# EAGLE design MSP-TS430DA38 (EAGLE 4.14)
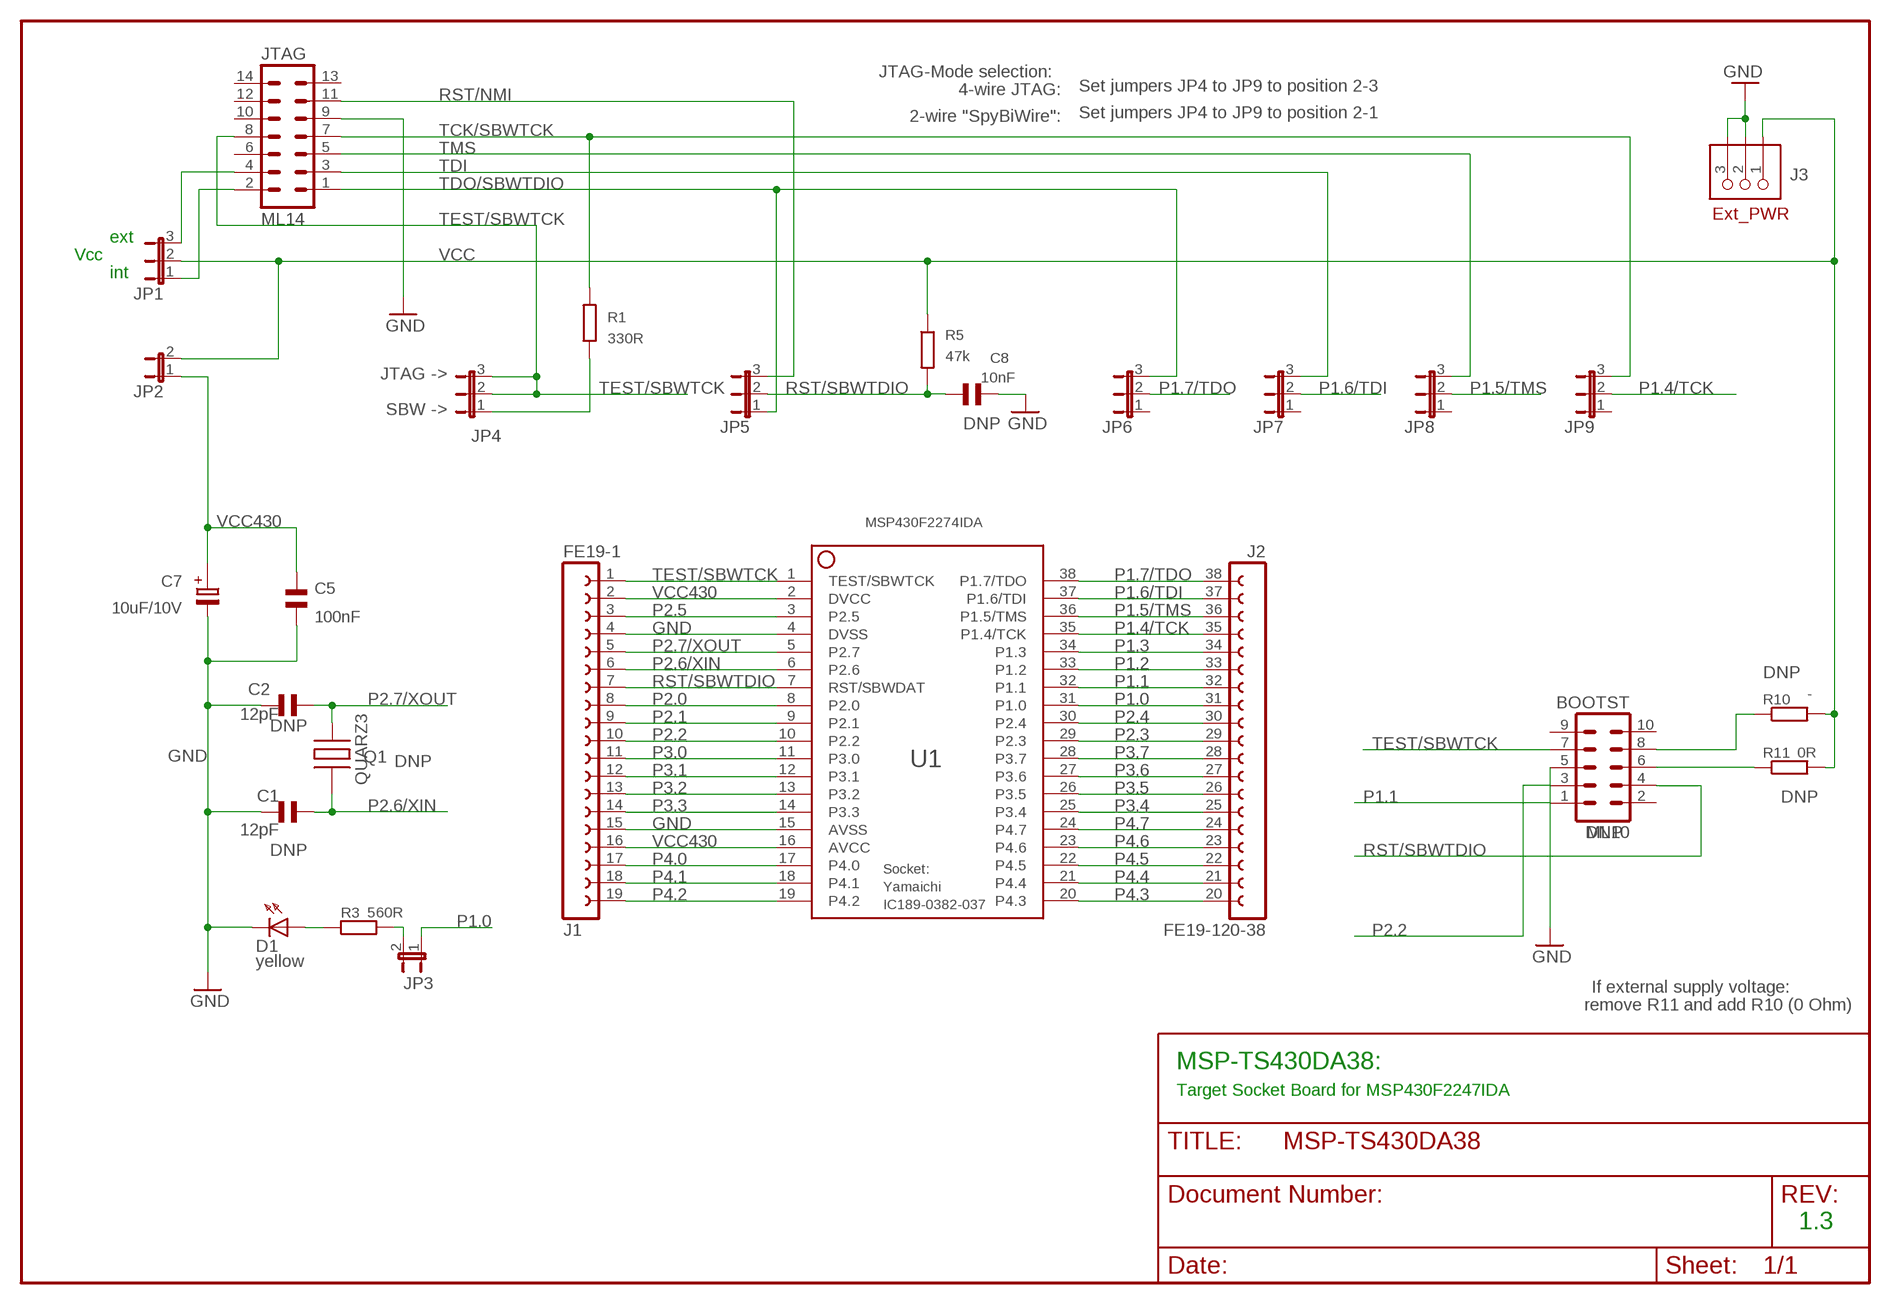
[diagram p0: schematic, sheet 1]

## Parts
BOOTST  ML10  [ML10]
C1  12pF  CSMD0805  [CSMD0805]
C2  12pF  CSMD0805  [CSMD0805]
C5  100nF  CSMD0805  [CSMD0805]
C7  10uF/10V  ELKO_1210  [1210ELKO]
C8  10nF  CSMD0805  [CSMD0805]
D1  yellow  LED_0805  [DIODE0805]
J1  FE19-1  [FE19-1-1]
J2  FE19-120-38  [FE19-2]
J3  PINHD-1X3  [PWR3]
JP1  JP2E  [JP2]
JP2  JP1E  [JP1]
JP3  JP1E  [JP1]
JP4  JP2E  [JP2]
JP5  JP2E  [JP2]
JP6  JP2E  [JP2]
JP7  JP2E  [JP2]
JP8  JP2E  [JP2]
JP9  JP2E  [JP2]
JTAG  ML14  [ML14]
Q1  QUARZ3  [QUARZ3]
R1  330R  R_0805  [0805]
R3  560R  R_0805  [0805]
R5  47k  R_0805  [0805]
R10  -  R_0805  [0805]
R11  0R  R_0805  [0805]
U1  MSP430F2274IDA  F2274_DA38  [IC189-0382-037]

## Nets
GND: BOOTST.5 C1.2 C2.2 C5.2 C7.- C8.1 D1.K(C) J1.4 J1.15 J3.2 J3.3 JTAG.9 U1.4(DVSS) U1.15(AVSS)
N$1: D1.A R3.1
N$2: JP4.1 R1.1
N$7: JP1.1 JTAG.2
N$23: JP1.3 JTAG.4
N$33: JP3.2 R3.2
N$42: BOOTST.8 R10.1
N$49: BOOTST.6 R11.1
P1.0: J2.31 JP3.1 U1.31(P1.0)
P1.1: BOOTST.1 J2.32 U1.32(P1.1)
P1.2: J2.33 U1.33(P1.2)
P1.3: J2.34 U1.34(P1.3)
P1.4/TCK: J2.35 JP9.2 U1.35(P1.4/TCK)
P1.5/TMS: J2.36 JP8.2 U1.36(P1.5/TMS)
P1.6/TDI: J2.37 JP7.2 U1.37(P1.6/TDI)
P1.7/TDO: J2.38 JP6.2 U1.38(P1.7/TDO)
P2.0: J1.8 U1.8(P2.0)
P2.1: J1.9 U1.9(P2.1)
P2.2: BOOTST.3 J1.10 U1.10(P2.2)
P2.3: J2.29 U1.29(P2.3)
P2.4: J2.30 U1.30(P2.4)
P2.5: J1.3 U1.3(P2.5)
P2.6/XIN: C1.1 J1.6 Q1.3 U1.6(P2.6)
P2.7/XOUT: C2.1 J1.5 Q1.4 U1.5(P2.7)
P3.0: J1.11 U1.11(P3.0)
P3.1: J1.12 U1.12(P3.1)
P3.2: J1.13 U1.13(P3.2)
P3.3: J1.14 U1.14(P3.3)
P3.4: J2.25 U1.25(P3.4)
P3.5: J2.26 U1.26(P3.5)
P3.6: J2.27 U1.27(P3.6)
P3.7: J2.28 U1.28(P3.7)
P4.0: J1.17 U1.17(P4.0)
P4.1: J1.18 U1.18(P4.1)
P4.2: J1.19 U1.19(P4.2)
P4.3: J2.20 U1.20(P4.3)
P4.4: J2.21 U1.21(P4.4)
P4.5: J2.22 U1.22(P4.5)
P4.6: J2.23 U1.23(P4.6)
P4.7: J2.24 U1.24(P4.7)
RST/NMI: JP5.3 JTAG.11
RST/SBWTDIO: BOOTST.4 C8.2 J1.7 JP5.2 R5.2 U1.7(RST/SBWDAT)
TCK/SBWTCK: JP9.3 JTAG.7 R1.2
TDI: JP7.3 JTAG.3
TDO/SBWTDIO: JP5.1 JP6.3 JTAG.1
TEST/SBWTCK: BOOTST.7 J1.1 JP4.2 JP4.3 JTAG.8 U1.1(TEST/SBWTCK)
TMS: JP8.3 JTAG.5
VCC: J3.1 JP1.2 JP2.2 R5.1 R10.2 R11.2
VCC430: C5.1 C7.+ J1.2 J1.16 JP2.1 U1.2(DVCC) U1.16(AVCC)
Unconnected: BOOTST.2 BOOTST.9 BOOTST.10 JP6.1 JP7.1 JP8.1 JP9.1 JTAG.6 JTAG.10 JTAG.12 JTAG.13 JTAG.14

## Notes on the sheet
- JTAG-Mode selection:
- 4-wire JTAG:
- Set jumpers JP4 to JP9 to position 2-3
- 2-wire "SpyBiWire":
- Set jumpers JP4 to JP9 to position 2-1
- Ext_PWR
- ext
- Vcc
- int
- JTAG ->
- SBW ->
- DNP
- DNP
- DNP
- DNP
- DNP
- DNP
- DNP
- Socket:
- Yamaichi
- IC189-0382-037
- If external supply voltage:
- remove R11 and add R10 (0 Ohm)
- MSP-TS430DA38:
- Target Socket Board for MSP430F2247IDA
- 1.3

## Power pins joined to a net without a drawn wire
GND: Q1.GND@1(GND) Q1.GND@2(GND) Q1.GND@3(GND)

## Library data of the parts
BOOTST = con-ml:ML10
C1 C2 C5 C8 = cap:CSMD0805
C7 = smd:ELKO_1210
D1 = smd:LED_0805
J1 J2 = con-lsta_extended:FE19-1
J3 = PINHEAD:PINHD-1X3
JP1 JP4-JP9 = jumper:JP2E: JUMPER
JP2 JP3 = jumper:JP1E: JUMPER
JTAG = con-ml:ML14
Q1 = MSP430:QUARZ3
R1 R3 R5 R10 R11 = smd:R_0805
U1 = yamaichi_new:F2274_DA38

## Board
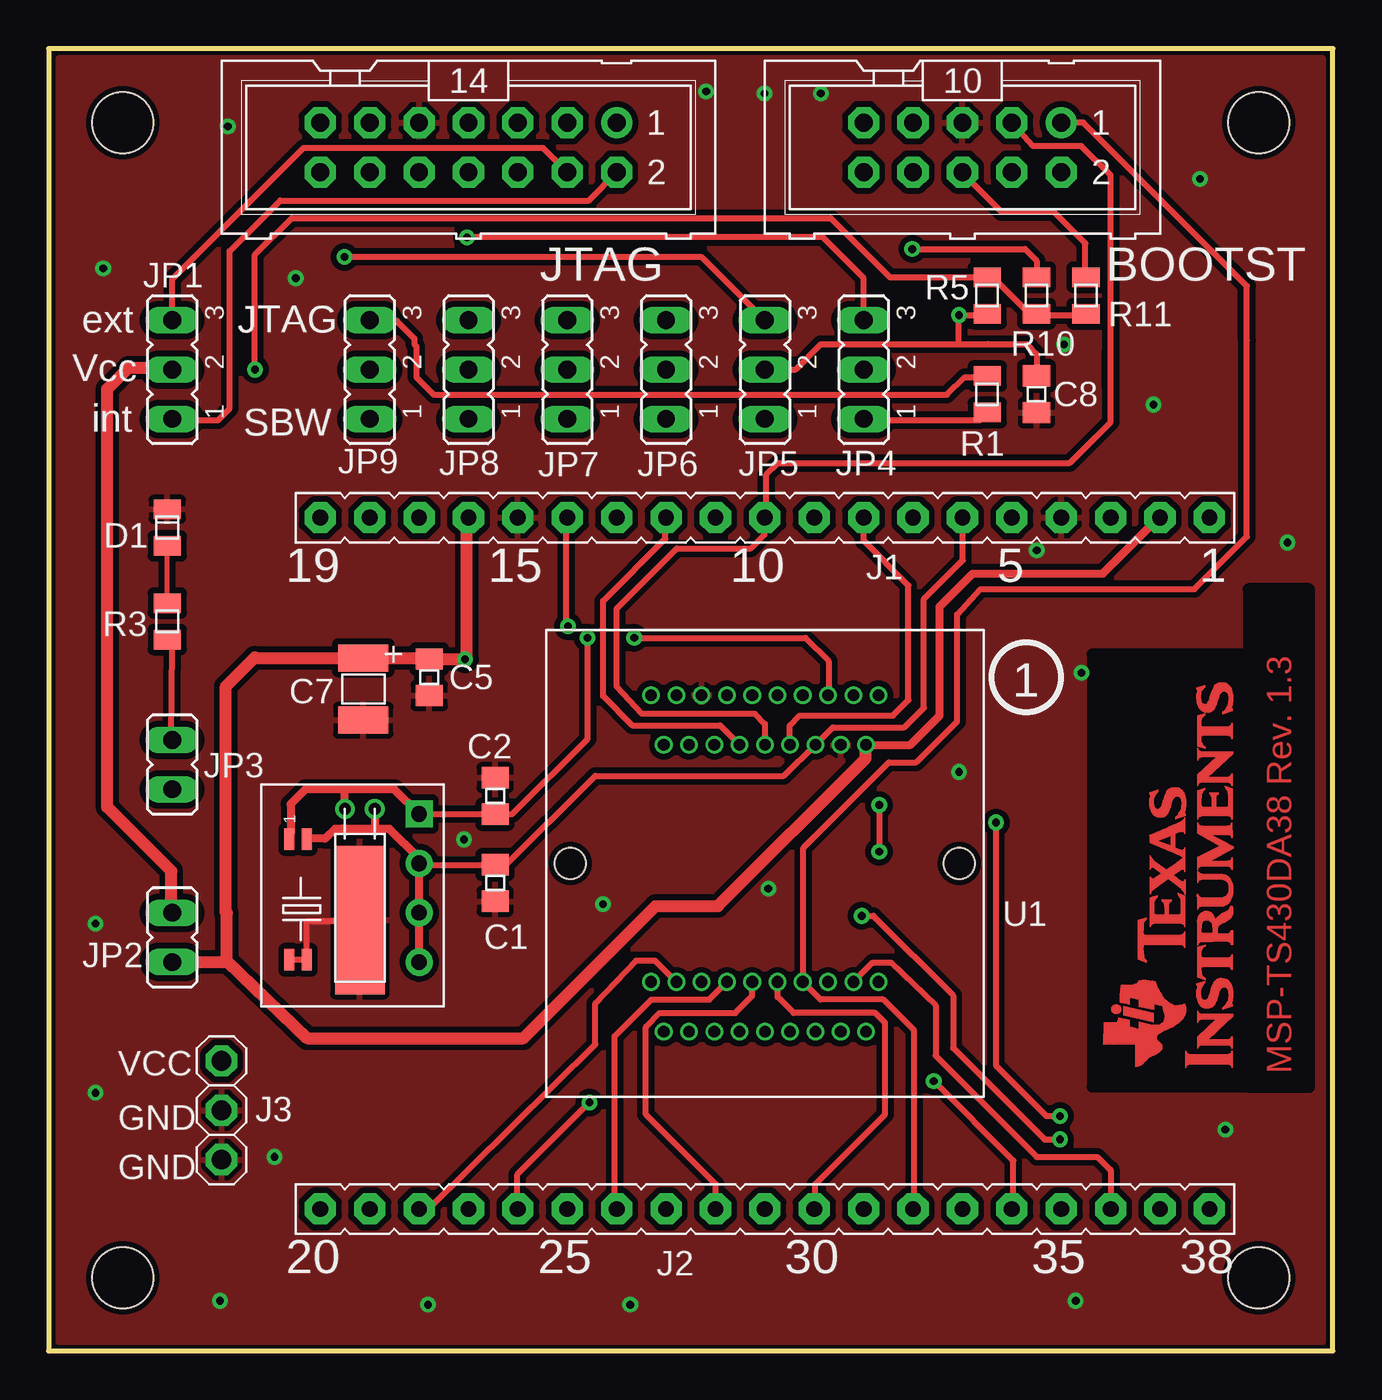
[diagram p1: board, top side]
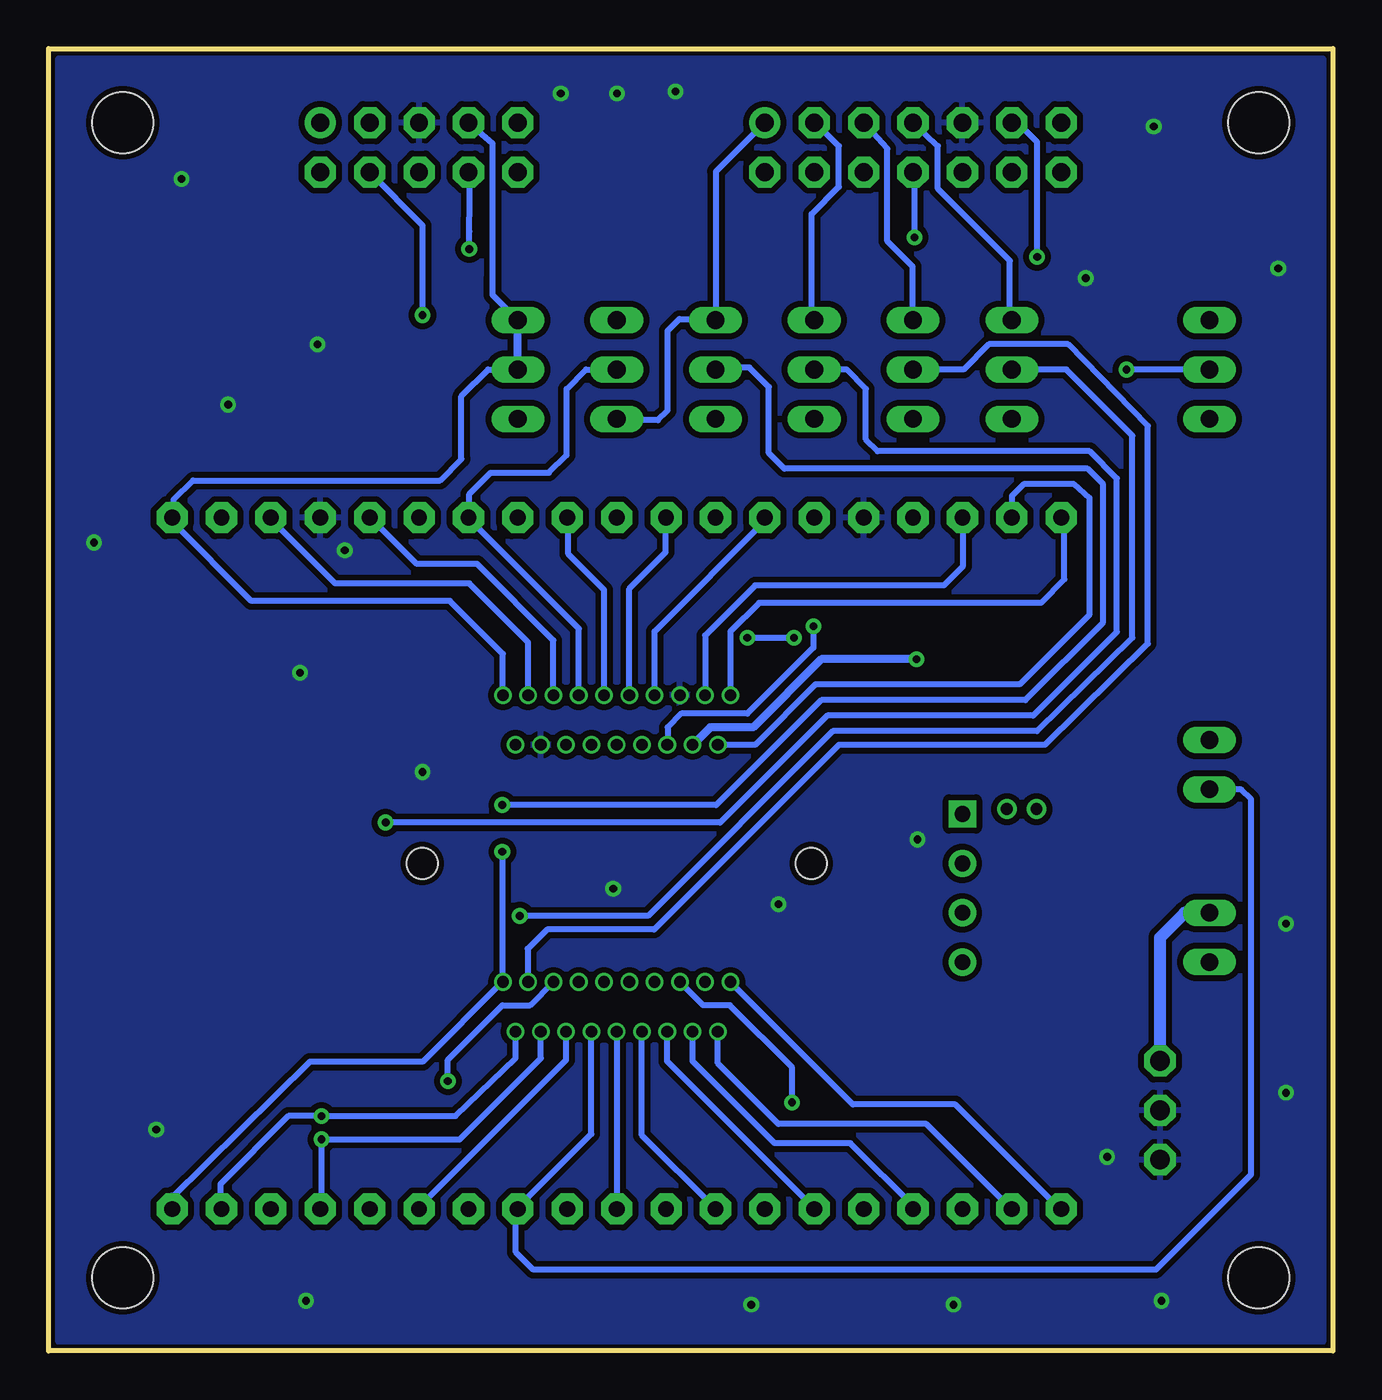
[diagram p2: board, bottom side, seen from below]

Size 66.04 x 66.99 mm. Coordinates in mm from the lower left corner, seen from the top.
Outline: 0,66.99 0,0 66.04,0 66.04,66.99 0,66.99
Copper layers (1*16): Top 0.035mm / dielectric 1.5mm / Bottom 0.035mm
Design rules "default": minimum track width 0.3mm, minimum drill 0.4mm, track to track 0.2mm, track to pad 0.2mm, pad to pad 0.2mm, via to via 0.2mm, smd to smd 8mil, copper to edge 0mil, drill to drill 8mil, minimum pad ring 6mil, minimum via ring 8mil, stop-mask expansion 4mil, vias tented up to drill 0.4mm, thermal gap 10mil
Holes 3.15 mm at 3.81,63.18 62.23,63.18 62.23,3.76 3.81,3.76
tRestrict: area 53.7,13.6 to 61.7,35.8; area 61.7,13.6 to 64.8,39.2

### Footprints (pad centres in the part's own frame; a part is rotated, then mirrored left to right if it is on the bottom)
ML10 = drill 0.914 pad 1.6 round: 1 -5.08,-1.27 | drill 0.914 pad 1.6 octagon: 2 -5.08,1.27; 3 -2.54,-1.27; 4 -2.54,1.27; 5 0,-1.27; 6 0,1.27; 7 2.54,-1.27; 8 2.54,1.27; 9 5.08,-1.27; 10 5.08,1.27
CSMD0805 = smd 1.092 x 1.397: 1 -0.94,0; 2 0.94,0
1210ELKO = smd 1.397 x 2.591: + 1.6,0; - -1.6,0
DIODE0805 = smd 1 x 1.4: A -0.94,0; K 0.94,0
FE19-1-1 = drill 0.813 pad 1.6 octagon: 1 -21.59,0; 2 -19.05,0; 3 -16.51,0; 4 -13.97,0; 5 -11.43,0; 6 -8.89,0; 7 -6.35,0; 8 -3.81,0; 9 -1.27,0; 10 1.27,0; 11 3.81,0; 12 6.35,0; 13 8.89,0; 14 11.43,0; 15 13.97,0; 16 16.51,0; 17 19.05,0; 18 21.59,0; 19 24.13,0
FE19-2 = drill 0.813 pad 1.6 octagon: 20 -25.4,0; 21 -22.86,0; 22 -20.32,0; 23 -17.78,0; 24 -15.24,0; 25 -12.7,0; 26 -10.16,0; 27 -7.62,0; 28 -5.08,0; 29 -2.54,0; 30 0,0; 31 2.54,0; 32 5.08,0; 33 7.62,0; 34 10.16,0; 35 12.7,0; 36 15.24,0; 37 17.78,0; 38 20.32,0
PWR3 = drill 1.016 pad 1.6 octagon: 1 -2.54,0; 2 0,0; 3 2.54,0
JP2 = drill 0.914 long: 1 -2.54,0; 2 0,0; 3 2.54,0
JP1 = drill 0.914 long: 1 0,-1.27; 2 0,1.27
ML14 = drill 0.914 pad 1.6 round: 1 -7.62,-1.27 | drill 0.914 pad 1.6 octagon: 2 -7.62,1.27; 3 -5.08,-1.27; 4 -5.08,1.27; 5 -2.54,-1.27; 6 -2.54,1.27; 7 0,-1.27; 8 0,1.27; 9 2.54,-1.27; 10 2.54,1.27; 11 5.08,-1.27; 12 5.08,1.27; 13 7.62,-1.27; 14 7.62,1.27
QUARZ3 = drill 0.813 pad 1.397 round: 1 -3.81,-1.27; 2 -1.27,-1.27; 3 1.27,-1.27 | drill 0.813 pad 1.397 square: 4 3.81,-1.27 | drill 0.61 pad 1.016 round: 5 4.064,1.016; 6 4.064,2.54 | smd 1.1 x 0.5: 7 2.517,4.513; 8 2.513,5.409; GND@1 -3.687,5.409; GND@2 -3.687,4.51 | smd 7.62 x 2.54: GND@3 -1.651,1.778
0805 = smd 1 x 1.4: 1 -0.94,0; 2 0.94,0
IC189-0382-037 = drill 0.6 round: 1 -8.65,5.85; 2 -6.1,5.2; 3 -8.65,4.55; 4 -6.1,3.9; 5 -8.65,3.25; 6 -6.1,2.6; 7 -8.65,1.95; 8 -6.1,1.3; 9 -8.65,0.65; 10 -6.1,0; 11 -8.65,-0.65; 12 -6.1,-1.3; 13 -8.65,-1.95; 14 -6.1,-2.6; 15 -8.65,-3.25; 16 -6.1,-3.9; 17 -8.65,-4.55; 18 -6.1,-5.2; 19 -8.65,-5.85; 20 6.1,-5.85; 21 8.65,-5.2; 22 6.1,-4.55; 23 8.65,-3.9; 24 6.1,-3.25; 25 8.65,-2.6; 26 6.1,-1.95; 27 8.65,-1.3; 28 6.1,-0.65; 29 8.65,0; 30 6.1,0.65; 31 8.65,1.3; 32 6.1,1.95; 33 8.65,2.6; 34 6.1,3.25; 35 8.65,3.9; 36 6.1,4.55; 37 8.65,5.2; 38 6.1,5.85 | hole 1.6: 0,10; 0,-10

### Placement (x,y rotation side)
BOOTST  46.99,61.91 180 top
C1  22.96,24.07 270 top
C2  22.96,28.55 90 top
C5  19.57,34.65 270 top
C7  16.18,34.05 90 top
C8  50.8,49.21 90 top
D1  6.1,42.35 90 top
J1  38.1,42.86 180 top
J2  39.37,7.3 0 top
J3  8.89,12.38 270 top
JP1  6.35,50.48 90 top
JP2  6.35,21.27 0 top
JP3  6.35,30.16 0 top
JP4  41.91,50.48 90 top
JP5  36.83,50.48 90 top
JP6  31.75,50.48 90 top
JP7  26.67,50.48 90 top
JP8  21.59,50.48 90 top
JP9  16.51,50.48 90 top
JTAG  21.59,61.91 180 top
Q1  17.78,23.81 90 top
R1  48.26,49.21 90 top
R3  6.1,37.53 270 top
R5  48.26,54.29 270 top
R10  50.8,54.29 270 top
R11  53.34,54.29 270 top
U1  36.83,25.08 270 top
U$1  [ORI2_2CM]  60.91,14.58 90 top

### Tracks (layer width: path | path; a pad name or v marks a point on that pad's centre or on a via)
GND  (via drill 0.4)
  Top 0.3: Q1.GND@1 13.23,20.12 13.24,20.11 13.24,20.12 Q1.GND@2 13.27,22.11 16,22.11 Q1.GND@3
  other vias: 52.21,51.78 50.81,41.18 56.81,48.68 63.71,41.58 59.21,60.28 46.81,29.78 53.11,34.88 2.41,21.98 11.61,9.98 28.51,22.98 37.01,23.78 2.41,13.28 8.81,2.58 19.51,2.38 60.51,11.38 52.81,2.58 29.91,2.38 33.81,64.78 36.81,64.68 39.71,64.68 9.21,62.98 2.81,55.68 12.71,55.18 21.36,26.31
  pour Bottom (isolate 0.305): 0.51,66.48 0.51,0.46 65.53,0.46 65.53,66.48
  pour Top (isolate 0.305): 0.51,66.48 0.51,0.46 65.53,0.46 65.53,66.48
N$1
  Top 0.254: R3.1 D1.A
N$2
  Top 0.3: 41.91,47.98 JP4.1 41.91,47.88 47.87,47.88 R1.1
N$7
  Top 0.3: JTAG.2 27.78,59.18 11.91,59.18 9.31,56.58 9.31,48.48 8.71,47.88 6.31,47.88 JP1.1
N$23
  Top 0.3: JP1.3 6.35,55.12 13.11,61.88 25.41,61.88 26.01,61.31 JTAG.4
N$33
  Top 0.3: R3.2 6.1,36.51 6.35,36.26 6.29,31.4 6.29,31.63 JP3.2
N$42  (via drill 0.4)
  Top 0.3: R10.1 50.81,55.28 50.81,56.08 50.21,56.68 v44.41,56.68
  Bottom 0.3: BOOTST.8 44.35,60.58 44.41,57.58 v44.41,56.68
N$49
  Top 0.3: R11.1 53.31,55.18 53.31,56.98
  Top 0.305: 53.31,56.98 51.71,58.58 49.01,58.58 47.01,60.58 47.01,60.62 BOOTST.6
P1.0
  Bottom 0.3: U1.31 38.13,11.16 41.91,7.38 | JP3.1 4.71,28.88 4.21,28.38 4.21,9.08 9.11,4.18 41.11,4.18 42.01,5.08 42.01,7.28 41.91,7.28
  Bottom 0.305: 41.91,7.28 J2.31 41.91,7.38
P1.1
  Top 0.3: 44.51,7.38 44.51,16.48 42.91,18.08 39.68,18.08 U1.32 38.81,18.98 38.81,25.88 43.21,30.28 44.61,30.28 46.71,32.38 46.71,37.88 47.91,39.18 58.91,39.18 61.61,41.88 61.61,51.98 | BOOTST.1 53.21,63.18 56.01,60.38
  Top 0.305: 61.61,51.98 61.61,54.78 56.01,60.38 | 44.51,7.38 44.45,7.38 J2.32
P1.2
  Bottom 0.3: U1.33 39.43,14.96 47.01,7.38
  Bottom 0.305: 47.01,7.38 46.99,7.38 J2.33
P1.3  (via drill 0.4)
  Top 0.3: v45.51,13.88 49.61,9.78 49.61,7.38
  Top 0.305: 49.61,7.38 49.53,7.38 J2.34
  Bottom 0.3: U1.34 41.28,17.78 42.71,17.78 45.51,14.98 v45.51,13.88
P1.4/TCK  (via drill 0.4)
  Top 0.3: v52.01,10.88 51.21,10.88 46.51,15.58 46.51,18.28 42.41,22.38 v41.81,22.38
  Bottom 0.3: U1.35 40.73,15.06 44.91,10.88 v52.01,10.88 52.01,7.28 52.11,7.38 52.07,7.38 | JP9.2 13.71,50.48 10.31,47.08 10.31,36.68 15.21,31.88 25.71,31.88 35.21,22.38 v41.81,22.38
  Bottom 0.305: 52.01,7.28 52.07,7.28 J2.35
P1.5/TMS
  Top 0.3: U1.36 42.38,19.98 43.31,19.98 45.61,17.78 45.61,15.18 50.81,9.98 53.91,9.98 54.58,9.31 54.61,9.28
  Top 0.305: 54.61,9.31 54.61,9.33 | 54.58,9.31 54.61,9.31 | 54.61,9.31 J2.36
  Bottom 0.3: JP8.2 18.99,50.48 17.69,51.78 13.61,51.78 9.51,47.58 9.51,36.38 14.81,31.18 25.41,31.18 34.91,21.68 40.41,21.68 41.41,20.68 41.41,18.98 U1.36
P1.6/TDI  (via drill 0.4)
  Top 0.3: v52.01,12.08 51.31,12.08 48.71,14.68 v48.71,27.18
  Bottom 0.3: U1.37 42.03,15.06 45.11,12.08 52.11,12.08 | 57.21,7.28 57.15,7.28 | 52.11,12.08 53.71,12.08 57.21,8.58 57.21,7.28 | 57.21,7.28 57.21,7.18 | v52.01,12.08 52.11,12.08 | JP7.2 25.01,50.48 24.01,49.48 24.01,46.88 23.41,46.28 12.51,46.28 11.11,44.88 11.11,36.98 15.41,32.68 26.01,32.68 31.51,27.18 v48.71,27.18
  Bottom 0.305: 57.21,7.18 57.15,7.18 J2.37
P1.7/TDO  (via drill 0.4)
  Top 0.3: v42.71,28.08 v42.71,25.68
  Bottom 0.3: 59.71,8 59.71,7.88 52.61,14.88 46.81,14.88 42.71,18.98 U1.38 42.71,19.11 v42.71,25.68 | JP6.2 31.75,50.58 30.01,50.58 29.01,49.58 29.01,46.18 28.21,45.38 12.61,45.38 11.81,44.58 11.81,37.48 15.81,33.48 26.31,33.48 31.71,28.08 v42.71,28.08
  Bottom 0.305: 59.71,7.88 59.69,7.88 J2.38
P2.0
  Top 0.3: U1.8 38.11,31.2 38.11,32.18 38.61,32.68 43.41,32.68 44.21,33.48 44.21,39.38 41.91,41.68
  Top 0.305: 41.91,41.68 J1.8
P2.1
  Bottom 0.3: U1.9 37.48,39.15 39.31,40.98 39.31,42.98 39.37,42.88
  Bottom 0.305: 39.37,42.88 J1.9
P2.2
  Top 0.3: U1.10 36.83,32.26 36.31,32.78 30.51,32.78 29.21,34.18 29.21,38.18 32.31,41.28 36.11,41.28 36.81,41.98 36.81,42.78 36.91,42.88 | 36.91,42.88 36.91,42.86 | 36.91,42.88 36.91,45.08 37.51,45.68 52.51,45.68 54.61,47.78 54.61,49.58 | 54.61,51.42 54.61,60.48 53.11,61.98 50.61,61.98 BOOTST.3
  Top 0.305: 54.61,49.58 54.61,51.42 | 36.91,42.88 36.83,42.88 J1.10
P2.3
  Bottom 0.3: U1.29 36.81,16.43 36.81,7.28
  Bottom 0.305: 36.81,7.28 36.83,7.28 J2.29
P2.4
  Top 0.3: U1.30 37.48,18.21 38.31,17.38 42.51,17.38 43.01,16.88 43.01,12.18 39.41,8.58 39.41,7.38
  Top 0.305: 39.41,7.38 39.37,7.38 J2.30
P2.5
  Bottom 0.3: U1.3 41.38,36.45 44.41,39.48 51.31,39.48 54.71,42.88 54.71,42.86
  Bottom 0.406: 54.71,42.88 54.61,42.88 J1.3
P2.6/XIN
  Top 0.3: 47.01,42.98 47.01,40.68 45.01,38.68 45.01,33.08 44.01,32.08 40.33,32.08 U1.6 39.41,31.18 37.81,29.58 28.11,29.58 23.29,24.76 C1.1 18.94,25.01 | 19.04,25.11 Q1.3 18.94,25.01 | 18.94,25.01
  Top 0.406: 47.01,42.98 46.99,42.98 J1.6
P2.7/XOUT  (via drill 0.4)
  Top 0.3: Q1.4 | Q1.4 C2.1 23.83,27.61 27.71,31.49 v27.71,36.68 | Q1.4 | U1.5 40.08,33.78 40.11,33.78 40.11,35.48 38.91,36.68 v30.11,36.68
  Bottom 0.3: U1.5 40.08,36.55 44.01,40.48 47.11,40.48 49.61,42.98 49.53,42.88 | v27.71,36.68 v30.11,36.68
  Bottom 0.406: 49.53,42.88 J1.5
P3.0
  Bottom 0.3: U1.11 36.18,39.21 34.31,41.08 34.31,42.98
  Bottom 0.305: 34.31,42.98 34.29,42.98 J1.11
P3.1
  Top 0.3: U1.12 34.53,32.18 30.01,32.18 28.51,33.68 28.51,38.58 31.71,41.78 31.71,42.88
  Top 0.305: 31.71,42.88 31.75,42.88 J1.12
P3.2
  Bottom 0.3: U1.13 34.88,37.01 29.11,42.78
  Bottom 0.305: 29.11,42.78 29.21,42.78 J1.13
P3.3  (via drill 0.4)
  Top 0.3: v26.71,37.28 26.61,37.38 26.61,42.98
  Top 0.305: 26.61,42.98 26.67,42.98 J1.14
  Bottom 0.3: U1.14 34.21,31.2 34.21,32.08 33.51,32.78 30.11,32.78 26.71,36.18 v26.71,37.28
P3.4
  Bottom 0.3: U1.25 34.23,14.9 26.71,7.38
  Bottom 0.305: 26.71,7.38 26.67,7.38 J2.25
P3.5
  Top 0.3: U1.26 33.98,18.08 31.01,18.08 29.11,16.18 29.11,7.28
  Top 0.305: 29.11,7.28 29.21,7.28 J2.26
P3.6
  Bottom 0.3: 31.75,7.28 31.81,7.38 35.53,11.1 U1.27
  Bottom 0.305: 31.75,7.28 J2.27
P3.7
  Top 0.3: U1.28 36.18,18.25 35.31,17.38 31.41,17.38 30.71,16.68 30.71,12.18 34.31,8.58 34.31,7.28
  Top 0.305: 34.31,7.28 34.29,7.28 J2.28
P4.0
  Bottom 0.3: U1.17 32.28,36.81 29.71,39.38 20.01,39.38 19.01,40.38 19.01,42.78 | 19.01,42.78 19.05,42.78 | 19.01,42.78 19.01,42.88
  Bottom 0.305: 19.01,42.88 19.05,42.88 J1.17
P4.1
  Bottom 0.3: U1.18 29.71,31.18 26.61,34.28 16.11,34.28 12.51,37.88 12.51,43.88 13.31,44.58 15.91,44.58 16.51,43.98
  Bottom 0.305: 16.51,43.98 J1.18
P4.2
  Bottom 0.3: U1.19 30.98,37.01 29.51,38.48 15.01,38.48 13.81,39.68 13.81,42.78 13.91,42.86
  Bottom 0.305: 13.91,42.86 J1.19
P4.3
  Bottom 0.3: U1.20 24.68,12.68 19.41,12.68 14.01,7.28
  Bottom 0.305: 14.01,7.28 13.97,7.28 J2.20
P4.4
  Bottom 0.3: U1.21 31.63,14.8 28.51,11.68 20.91,11.68 16.51,7.28
  Bottom 0.305: 16.51,7.28 J2.21
P4.5
  Top 0.3: U1.22 31.18,20.08 30.21,20.08 28.11,17.88 28.11,15.78 19.51,7.28 19.11,7.28
  Top 0.305: 19.11,7.28 19.05,7.28 J2.22
P4.6
  Bottom 0.3: U1.23 32.93,14.9 28.71,10.68 24.81,10.68 21.51,7.38 21.59,7.28
  Bottom 0.305: 21.59,7.28 J2.23
P4.7  (via drill 0.4)
  Top 0.3: v27.81,12.78 24.11,9.08 24.11,7.28
  Top 0.305: 24.11,7.28 24.13,7.28 J2.24
  Bottom 0.3: U1.24 32.38,17.78 31.01,17.78 27.81,14.58 v27.81,12.78
RST/NMI  (via drill 0.4)
  Top 0.3: JP5.3 33.57,56.28 v15.21,56.28
  Bottom 0.3: JTAG.11 16.41,63.45 16.41,63.38 15.21,62.18 v15.21,56.28
RST/SBWTDIO  (via drill 0.4)
  Top 0.3: 36.71,50.48 JP5.2 38.41,50.48 39.71,51.78 46.81,51.78 | C8.2 50.81,51.28 50.31,51.78 48.29,51.78 | 46.81,51.78 48.29,51.78 | R5.2 48.31,53.28 v46.81,53.28 46.81,51.78 | 48.29,51.78 48.31,51.8
  Bottom 0.3: 44.51,42.86 44.51,42.88 38.78,37.15 U1.7 | JP5.2 38.41,50.48 39.41,49.48 39.41,46.08 40.31,45.18 43.31,45.18 44.41,44.08 44.41,42.86 | BOOTST.4 46.81,57.89 v46.81,53.28
  Bottom 0.305: 44.51,42.88 44.45,42.88 J1.7
  Bottom 0.406: J1.7 44.41,42.86
TCK/SBWTCK
  Top 0.3: R1.2 48.19,50.08 47.11,50.08 46.19,49.18 19.81,49.18 18.91,50.08 18.91,51.68 18.81,51.78 18.81,52.08 17.91,52.98 16.51,52.98 | 16.41,52.98 16.51,52.98 | 16.51,52.98 JP9.3
  Bottom 0.3: JTAG.7 20.31,61.97 20.31,59.78 16.61,56.08 16.61,52.88 JP9.3
TDI
  Bottom 0.3: JP7.3 26.81,53.16 26.81,58.48 25.41,59.88 25.41,61.98 26.71,63.28 JTAG.3
TDO/SBWTDIO
  Bottom 0.3: 31.71,60.68 31.71,53.06 JP6.3 31.81,53.08 33.61,53.08 34.21,52.48 34.21,48.38 34.71,47.88 36.91,47.88 | 36.91,47.88 37.01,47.88 | 36.91,47.88 JP5.1
  Bottom 0.305: 31.71,60.68 JTAG.1
TEST/SBWTCK  (via drill 0.4)
  Top 0.3: JP4.3 41.91,55.18 39.81,57.28 v21.51,57.28
  Bottom 0.3: U1.1 42.68,35.85 45.41,38.58 55.61,38.58 59.71,42.68 | 44.81,45.88 45.91,44.78 58.61,44.78 59.61,43.78 59.61,42.88 59.71,42.88 | BOOTST.7 43.21,62.11 43.21,55.18 | JTAG.8 21.59,60.78 21.61,60.68 21.51,60.78 v21.51,57.28
  Bottom 0.305: 59.71,42.88 59.69,42.88 J1.1 | 43.21,55.18 43.21,54.32 JP4.3 | 44.81,45.88 44.81,49.1 43.43,50.48 JP4.2
  Bottom 0.406: 59.71,42.68 59.69,42.68 J1.1 | JP4.2 JP4.3
TMS
  Bottom 0.3: JTAG.5 22.91,61.83 22.91,57.08 21.61,55.78 21.61,53.08 JP8.3
VCC  (via drill 0.4)
  Top 0.3: 6.51,50.58 6.41,50.58 JP1.2 | 50.81,53.38 50.81,53.28 53.27,53.28 R11.2 | 50.81,53.38 R10.2 | 50.81,53.38 50.41,53.38 48.61,55.18 48.31,55.18 R5.1 43.26,55.23 40.21,58.28 12.51,58.28 10.61,56.38 v10.61,50.48
  Top 0.406: JP2.2 6.31,22.58
  Top 0.61: 6.31,22.58 6.31,24.68 3.01,27.98 3.01,49.48 4.11,50.58 6.41,50.58
  Bottom 0.3: 6.31,50.48 JP1.2 v10.61,50.48
  Bottom 0.61: J3.1 8.89,21.27 7.62,22.54 JP2.2
VCC430  (via drill 0.4)
  Top 0.3: v21.41,35.58 21.51,35.58
  Top 0.305: 13.31,16.08 13.34,16.05 | 42.01,30.48 42.01,30.58 | 13.31,16.08 | 10.61,35.68 10.64,35.65 | 19.6,35.59 19.61,35.58 | 19.6,35.59 C5.1 | 19.54,35.65 19.6,35.59 | v21.4,35.59 v21.41,35.58 | 21.51,42.78 21.59,42.78 J1.16
  Top 0.406: U1.2 44.31,31.18 45.81,32.68 45.81,38.28 47.51,39.98 54.21,39.98 57.11,42.88 57.15,42.88 J1.2
  Top 0.61: 21.51,35.58 21.51,42.78 | 42.01,30.58 U1.2 | 9.16,20.07 13.31,16.08 24.41,16.08 31.21,22.88 34.41,22.88 42.01,30.48 | 10.61,35.68 9.11,34.18 9.11,22.51 9.14,22.54 9.16,22.52 9.16,20.07 | 10.64,35.65 C7.+ 19.54,35.65 | C5.1 v21.4,35.59 | 9.16,20.07 9.16,20.02 9.14,20 JP2.1
  Bottom 0.406: U1.16 32.03,32.08 29.81,32.08 26.31,35.58 v21.41,35.58

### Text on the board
Top: MSP-TS430DA38 Rev. 1.3
tPlace: ext | JTAG | Vcc | int | SBW | 19 | 15 | 10 | 5 | 1 | 1 | 20 | 25 | 30 | 35 | 38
